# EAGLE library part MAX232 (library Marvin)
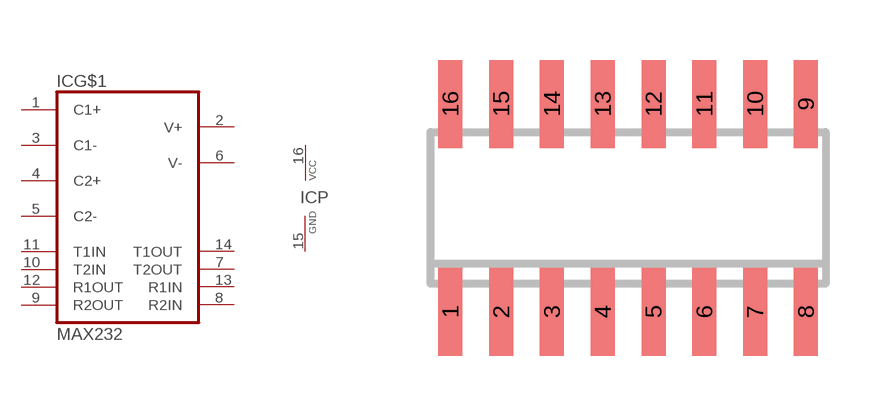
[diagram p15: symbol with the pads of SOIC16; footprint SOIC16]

Designator prefix IC; gates G$1=MAX232 P=VCC_GND

## MAX232  [SOIC16]
1  G$1:C1+
2  G$1:V+
3  G$1:C1-
4  G$1:C2+
5  G$1:C2-
6  G$1:V-
7  G$1:T2OUT  out
8  G$1:R2IN  in
9  G$1:R2OUT  out
10  G$1:T2IN  in
11  G$1:T1IN  in
12  G$1:R1OUT  out
13  G$1:R1IN  in
14  G$1:T1OUT  out
15  P:GND  pwr
16  P:VCC  pwr

## Footprint SOIC16 (pad centres in mm)
smd 0.6 x 2.2: 1 -4.445,-2.6; 2 -3.175,-2.6; 3 -1.905,-2.6; 4 -0.635,-2.6; 5 0.635,-2.6; 6 1.905,-2.6; 7 3.175,-2.6; 8 4.445,-2.6; 9 4.445,2.6; 10 3.175,2.6; 11 1.905,2.6; 12 0.635,2.6; 13 -0.635,2.6; 14 -1.905,2.6; 15 -3.175,2.6; 16 -4.445,2.6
